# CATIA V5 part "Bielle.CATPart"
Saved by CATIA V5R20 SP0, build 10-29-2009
Part number: Bielle
Bounding box of the stored display mesh (mm): x 0 to 2, y 8.616 to 27.406, z 2.02 to 6.529
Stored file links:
  C:\Users\MATT\Desktop\CATIA_Projet_IAO\CATIA FINAL\Bielle.CATPart
  C:\Users\MATT\Desktop\CATIA_Projet_IAO\CATIA FINAL\mderemetz.CATProduct
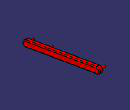
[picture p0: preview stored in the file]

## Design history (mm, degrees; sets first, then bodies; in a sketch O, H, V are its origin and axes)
External parameters (linked from other documents)
  External.AC = 3 mm
  External.CoeffAC = 3
  External.Epaisseur = 1 mm
Set1
  Sketch1 on Plane1, origin (1, 0, 0), H (0, 1, 0), V (0, 0, 1)
    construction line L1 (9.3657, 2.7702) -> (26.6559, 5.7791)
    point P1 (9.3657, 2.7702)
    point P2 (26.6559, 5.7791)
    line L2 (9.2371, 3.5091) -> (26.5273, 6.5179)
    line L3 (26.7844, 5.0402) -> (9.4943, 2.0313)
    arc A1 centre (26.6559, 5.7791) radius 0.75 from (26.5273, 6.5179) to (26.7844, 5.0402) cw
    arc A2 centre (9.3657, 2.7702) radius 0.75 from (9.4943, 2.0313) to (9.2371, 3.5091) cw
    reference projected point E1 (9.3657, 2.7702) from Point1
    reference projected point E2 (26.6559, 5.7791) from Point2
    distance L2 L3 = 1.5 {= 1.5*External.AC /3}
    tangency: A1 L2, A2 L2, A1 L3, A2 L3
    parallelism: L1 L2
    coincidence: P1 E1, P2 E2
Set2
  Plane1 "Plan_Sec": linked copy from another document
  Point1 "D": linked copy from another document
  Point2 "B": linked copy from another document
  Plane2 "Plan_Ter": linked copy from another document
  Point3 "C": linked copy from another document
Body1 (main body)
  Pad1: profile Sketch1, direction (1, 0, 0), up to Plane2
  Fillet1: radius 0.2 {= 0.2mm*External.CoeffAC /3}, on edge [end face of Pad1 | face of Pad1 from Sketch1.L2]; edge [start face of Pad1 | face of Pad1 from Sketch1.L2]; edge [face of Pad1 from Sketch1.A2 | end face of Pad1]; edge [start face of Pad1 | face of Pad1 from Sketch1.A2]; edge [end face of Pad1 | face of Pad1 from Sketch1.L3]; edge [face of Pad1 from Sketch1.A1 | end face of Pad1]; edge [start face of Pad1 | face of Pad1 from Sketch1.A1]; edge [start face of Pad1 | face of Pad1 from Sketch1.L3]
  Sketch2 on start face of Pad1, origin (1, 0, 0), H (0, -1, 0), V (0, 0, 1)
    circle A1 centre (-9.3657, 2.7702) radius 0.25
    point P1 (-9.3657, 2.7702)
    circle A2 centre (-13.9469, 3.5674) radius 0.25
    point P2 (-13.9469, 3.5674)
    circle A3 centre (-26.6559, 5.7791) radius 0.25
    point P3 (-26.6559, 5.7791)
    reference projected point E1 (-9.3657, 2.7702) from Point1
    reference projected point E2 (-13.9469, 3.5674) from Point3
    reference projected point E3 (-26.6559, 5.7791) from Point2
    radius A1 = 0.25 {= 0.5*External.AC /6}
    radius A2 = 0.25 {= 0.5*External.AC /6}
    radius A3 = 0.25 {= 0.5*External.AC /6}
    coincidence: P1 E1, P2 E2, P3 E3
  Pad2: profile Sketch2, direction (-1, 0, 0), length 1 {= External.Epaisseur}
